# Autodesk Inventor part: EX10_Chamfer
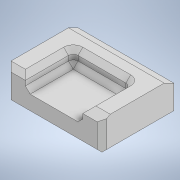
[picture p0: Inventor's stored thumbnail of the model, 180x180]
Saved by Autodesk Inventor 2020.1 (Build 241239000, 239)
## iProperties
Created: 2019-10
Part Number: EX10_Chamfer
Material: Generic
Document SubType Name: Modeling
Designer: Synergysoft Dell02
Density: 1 g/cm^3
Appearance: Default
Author: Synergysoft Dell02
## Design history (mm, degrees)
sketch "Sketch1"
  geometry: L1 (50, -37.5)-(-50, -37.5); L2 (-50, -37.5)-(-50, 37.5); L3 (-50, 37.5)-(50, 37.5); L4 (50, 37.5)-(50, -37.5); L5 (50, -37.5)-(-50, 37.5); L6 (-50, -37.5)-(50, 37.5); L7 (30, 37.5)-(-30, 37.5); L8 (-30, 37.5)-(-30, -12.5); L9 (-30, -12.5)-(30, -12.5); L10 (30, -12.5)-(30, 37.5); 2 further points
  constraints: 20 end point, 4 parallel, 2 horizontal, 2 midpoint, 2 perpendicular, 1 point on line
  dimensions: "d0" = 100 distance of L2.end L3.end; "d1" = 75 distance of L1.end L2.end; "d2" = 60 distance of L9.end L8.end; "d3" = 50 distance of L8.end L7.end; "d4" = 20 distance between parallel lines of L10 L4
extrude "Extrusion1" new body sketch "Sketch1" distance "d5" = 35; taper "d6" = 0 deg
extrude "Extrusion2" cut sketch "Sketch1" stored distance "d7" = 15; taper "d8" = 0 deg
chamfer "Chamfer1" distance "d9" = 5; stored, may be unused: second distance "d10" = 2, angle "d11" = 45 deg
chamfer "Chamfer2" distance "d12" = 5; stored, may be unused: second distance "d13" = 2, angle "d14" = 60 deg
chamfer "Chamfer3" distance "d15" = 10; stored, may be unused: second distance "d16" = 5, angle "d17" = 60 deg
fillet "Fillet1" dims "d18" = 5
chamfer "Chamfer4" distance "d19" = 5; stored, may be unused: second distance "d20" = 5, angle "d21" = 60 deg
chamfer "Chamfer5" distance "d22" = 5; stored, may be unused: second distance "d23" = 5, angle "d24" = 60 deg
chamfer "Chamfer6" distance "d25" = 5; stored, may be unused: second distance "d26" = 5, angle "d27" = 60 deg
chamfer "Chamfer7" distance "d28" = 5; stored, may be unused: second distance "d29" = 5, angle "d30" = 60 deg
body "Solid1"
